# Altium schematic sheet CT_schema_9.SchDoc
size 254 x 194 mm
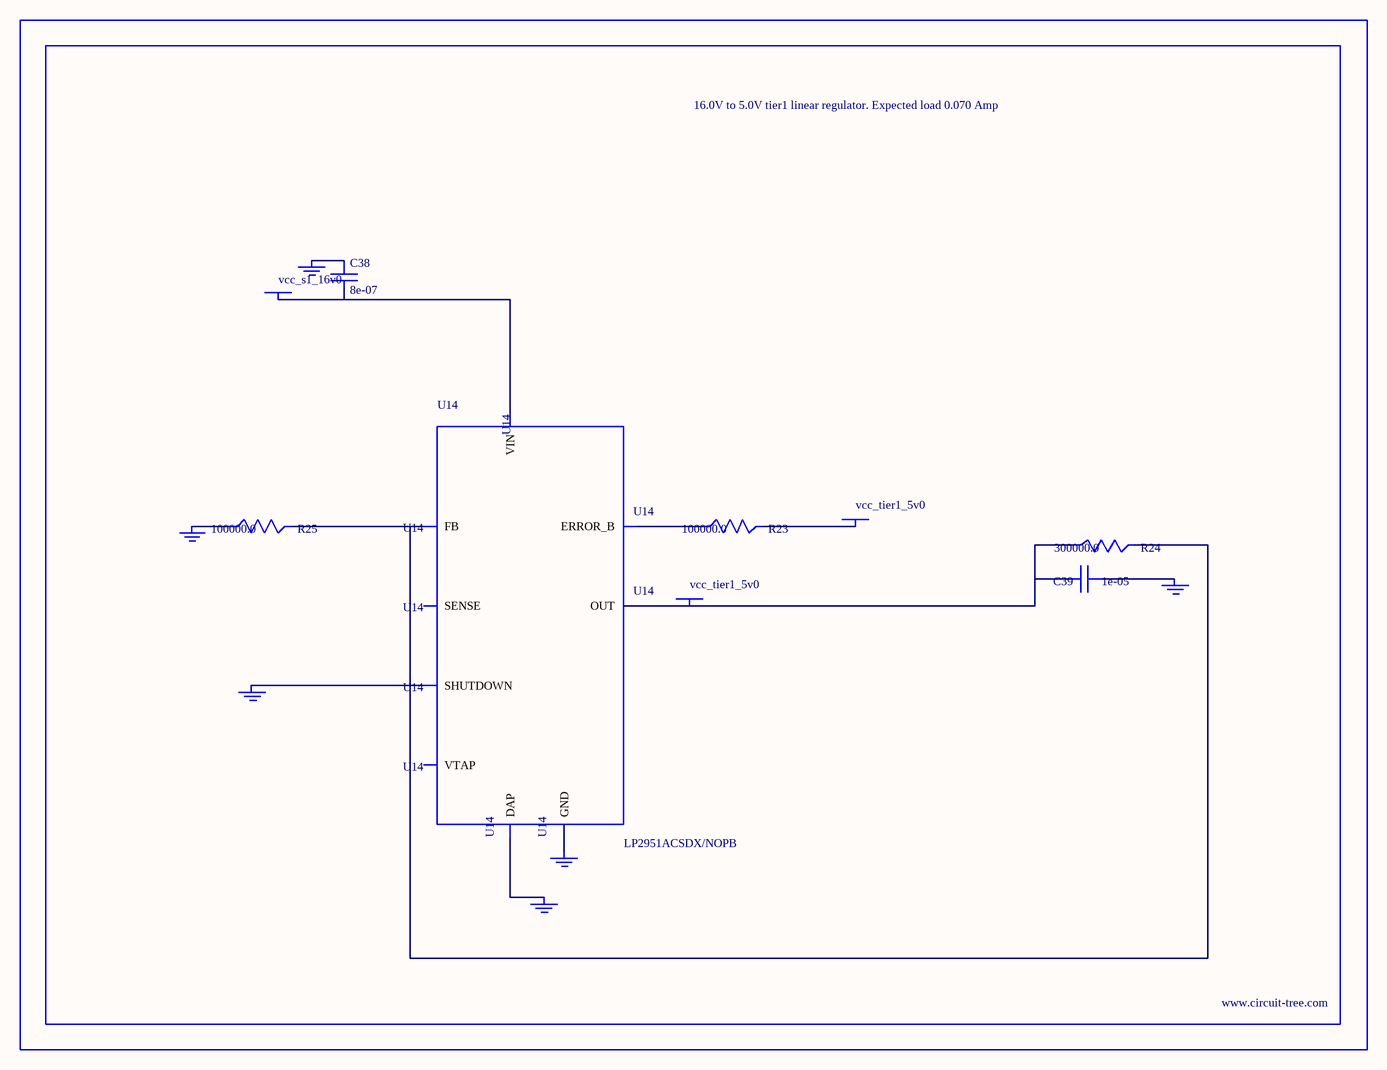
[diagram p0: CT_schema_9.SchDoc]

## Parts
BORDER8  (no value)
C38  8e-07  [R0603]
C39  1e-05  [C1210]
GND_INSTANCE_8_0  (no value)
GND_INSTANCE_8_1  (no value)
GND_INSTANCE_8_2  (no value)
GND_INSTANCE_8_3  (no value)
GND_INSTANCE_8_4  (no value)
GND_INSTANCE_8_5  (no value)
POWER_INSTANCE_8_0  vcc_tier1_5v0
POWER_INSTANCE_8_1  vcc_s1_16v0
POWER_INSTANCE_8_2  vcc_tier1_5v0
R23  100000.0  [R0603]
R24  300000.0  [R0603]
R25  100000.0  [R0603]
U14  LP2951ACSDX/NOPB  [WSON-8]

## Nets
NetC38_1: C38.1 GND_INSTANCE_8_3.0(GND)
NetC38_2: C38.2 POWER_INSTANCE_8_1.0(PWR) U14.8(VIN)
NetC39_1: C39.1 GND_INSTANCE_8_0.0(GND)
NetC39_2: C39.2 POWER_INSTANCE_8_2.0(PWR) R24.1 U14.1(OUT)
NetGND_INSTANCE_8_1_0: GND_INSTANCE_8_1.0(GND) U14.3(SHUTDOWN)
NetGND_INSTANCE_8_2_0: GND_INSTANCE_8_2.0(GND) R25.1
NetGND_INSTANCE_8_4_0: GND_INSTANCE_8_4.0(GND) U14.PAD(DAP)
NetGND_INSTANCE_8_5_0: GND_INSTANCE_8_5.0(GND) U14.4(GND)
NetPOWER_INSTANCE_8_0_0: POWER_INSTANCE_8_0.0(PWR) R23.2
NetR23_1: R23.1 U14.5(ERROR_B)
NetR24_2: R24.2 R25.2 U14.7(FB)

Not connected (* = marked no-connect by the designer): U14 2(SENSE) 6(VTAP)

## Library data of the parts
BORDER8 = BORDER_PAGE8
C38 = C38
C39 = GRM32DR61E106MA12L
GND_INSTANCE_8_0-GND_INSTANCE_8_5 = GND
POWER_INSTANCE_8_0-POWER_INSTANCE_8_2 = PWR
R23 R25 = RC0603JR-07100KL
R24 = RC0603JR-07300KL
